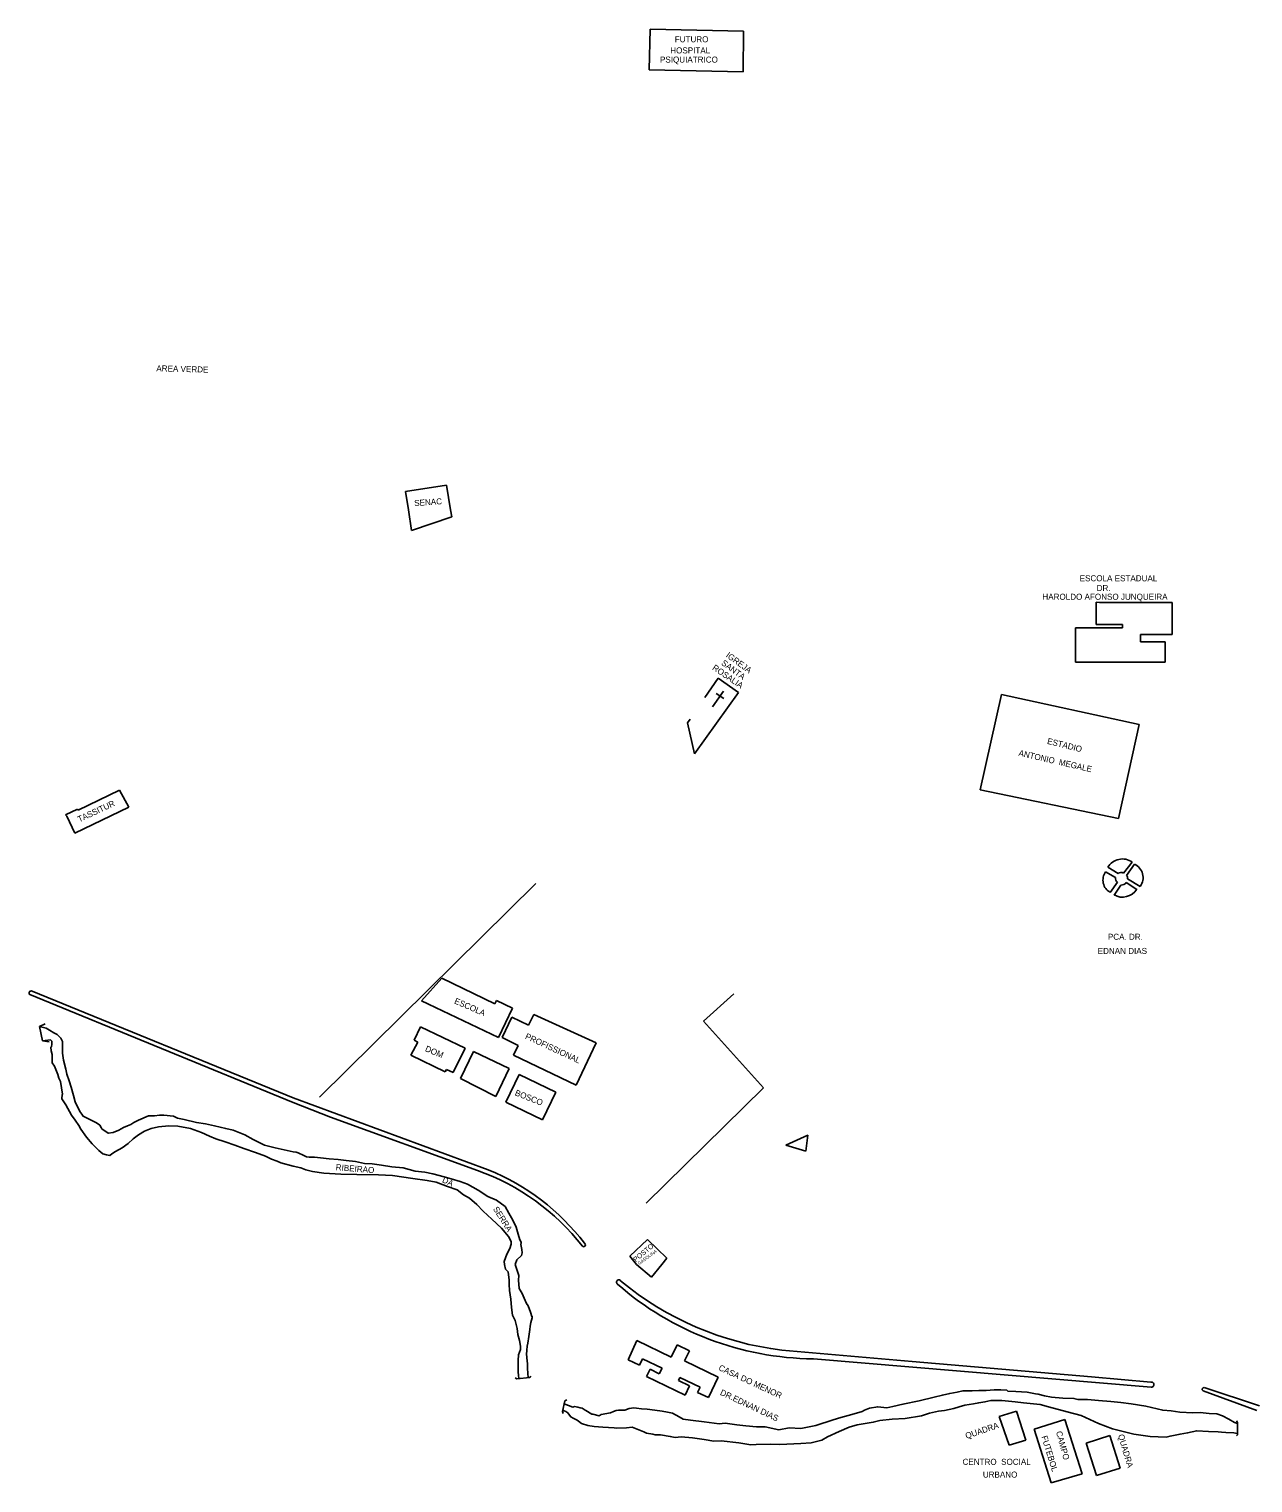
# Model space of a CAD drawing. Extents: x 325899 to 363134, y 7578590 to 7592502.
# Drawn here: x 339906 to 340717, y 7589857 to 7590820 of the extents above; entities that cross this region are included whole.
import ezdxf

# ---------------------------------------------------------------- set-up
doc = ezdxf.new("R2010")
doc.units = 0
for name, color, linetype in [('EDIFEXISTENT', 7, 'Continuous'), ('EDIFIDENTIF', 7, 'Continuous'), ('EDIFOBRAEXIS', 7, 'Continuous')]:
    doc.layers.add(name, color=color, linetype=linetype)

msp = doc.modelspace()

# ---------------------------------------------------------------- linework, layer by layer
at = {"layer": 'EDIFEXISTENT'}
for p, q in [((340317.19, 7590793.38), (340317.81, 7590820.28)), ((340317.81, 7590820.28), (340379.57, 7590818.85)), ((340379.57, 7590818.85), (340379.38, 7590791.94)), ((340379.38, 7590791.94), (340317.19, 7590793.38)), ((340155.84, 7590514.01), (340182.95, 7590518.24)), ((340182.95, 7590518.24), (340185.51, 7590501.91)), ((340157.73, 7590501.91), (340155.84, 7590514.01)), ((340157.73, 7590501.91), (340159.6, 7590488.12)), ((340159.6, 7590488.12), (340186.34, 7590497.29)), ((340186.34, 7590497.29), (340185.51, 7590501.91)), ((340613.33, 7590425.93), (340613.33, 7590440.74)), ((340613.33, 7590440.74), (340615.42, 7590440.43)), ((340615.42, 7590440.43), (340663.68, 7590440.43)), ((340663.68, 7590440.43), (340663.68, 7590419.3)), ((340599.65, 7590400.87), (340599.65, 7590423.61)), ((340599.65, 7590423.61), (340630.66, 7590423.61)), ((340630.66, 7590425.93), (340613.33, 7590425.93)), ((340630.66, 7590423.61), (340630.66, 7590425.93)), ((340663.68, 7590419.3), (340642.69, 7590419.3)), ((340642.69, 7590419.3), (340642.69, 7590414.33)), ((340642.69, 7590414.33), (340658.91, 7590414.33)), ((340658.91, 7590414.33), (340658.91, 7590400.87)), ((340658.91, 7590400.87), (340599.65, 7590400.87)), ((340362.78, 7590390.31), (340354.02, 7590377.55)), ((340376.25, 7590380.89), (340362.78, 7590390.31)), ((340347.07, 7590340.32), (340376.25, 7590380.89)), ((340359.01, 7590371.43), (340366.45, 7590381.73)), ((340361.45, 7590380.18), (340366.65, 7590376.78)), ((340536.46, 7590316.33), (340550.6, 7590379.45)), ((340550.6, 7590379.45), (340641.63, 7590359.66)), ((340344.23, 7590363.29), (340342.44, 7590360.67)), ((340342.44, 7590360.67), (340347.07, 7590340.32)), ((340641.63, 7590359.66), (340628.13, 7590297.31)), ((339938.84, 7590302.94), (339966.38, 7590316.2)), ((339966.38, 7590316.2), (339972.45, 7590304.99)), ((340628.13, 7590297.31), (340536.46, 7590316.33)), ((339930.59, 7590299.91), (339938.36, 7590303.65)), ((339972.45, 7590304.99), (339936.71, 7590287.75)), ((339938.36, 7590303.65), (339938.84, 7590302.94)), ((339931.38, 7590298.87), (339930.59, 7590299.91)), ((339936.71, 7590287.75), (339931.38, 7590298.87)), ((340241.99, 7590254.42), (340098.67, 7590112.92)), ((340166.42, 7590176.72), (340179.82, 7590191.56)), ((340179.82, 7590191.56), (340214.96, 7590174.71)), ((340373.26, 7590181.28), (340353.14, 7590163.2)), ((340217.35, 7590152.31), (340166.42, 7590176.72)), ((340166.42, 7590176.72), (340170.59, 7590174.72)), ((340214.96, 7590174.71), (340215.98, 7590176.84)), ((340215.98, 7590176.84), (340226.65, 7590171.72)), ((340226.65, 7590171.72), (340217.35, 7590152.31)), ((339917.07, 7590161.46), (339913.24, 7590159.66)), ((339913.24, 7590159.66), (339915.35, 7590150.11)), ((340161.37, 7590150.52), (340165.67, 7590159.49)), ((340165.67, 7590159.49), (340195.21, 7590145.33)), ((340226.17, 7590165.75), (340219.69, 7590152.24)), ((340237.21, 7590160.46), (340226.17, 7590165.75)), ((340240.64, 7590167.61), (340237.21, 7590160.46)), ((340282.12, 7590148.81), (340240.64, 7590167.61)), ((340353.14, 7590163.2), (340392.92, 7590118.92)), ((339915.35, 7590150.11), (339919.59, 7590149.57)), ((339919.59, 7590149.57), (339919.59, 7590149.57)), ((340159.26, 7590140.58), (340163.94, 7590149.29)), ((340163.94, 7590149.29), (340161.37, 7590150.52)), ((340219.69, 7590152.24), (340230.34, 7590147.14)), ((340268.69, 7590120.79), (340282.12, 7590148.81)), ((340182.1, 7590129.63), (340159.26, 7590140.58)), ((340195.21, 7590145.33), (340187.41, 7590129.06)), ((340192.1, 7590125.19), (340200.69, 7590143.12)), ((340200.69, 7590143.12), (340224.42, 7590131.74)), ((340230.34, 7590147.14), (340227.23, 7590140.66)), ((340227.23, 7590140.66), (340268.69, 7590120.79)), ((340182.87, 7590131.24), (340182.1, 7590129.63)), ((340187.41, 7590129.06), (340182.87, 7590131.24)), ((340224.42, 7590131.74), (340215.55, 7590113.25)), ((340215.55, 7590113.25), (340192.1, 7590125.19)), ((340222.17, 7590109.57), (340230.93, 7590127.85)), ((340230.93, 7590127.85), (340255.21, 7590116.21)), ((340255.21, 7590116.21), (340246.42, 7590097.88)), ((340392.92, 7590118.92), (340315.23, 7590042.72)), ((340246.42, 7590097.88), (340222.17, 7590109.57)), ((340304.35, 7590007.49), (340316.13, 7590018.45)), ((340316.13, 7590018.45), (340328.92, 7590006.24)), ((340308.82, 7590001.91), (340304.35, 7590007.49)), ((340328.92, 7590006.24), (340325.49, 7590001.91)), ((340308.82, 7590001.91), (340318.68, 7589993.68)), ((340318.68, 7589993.68), (340325.49, 7590001.91)), ((340303.14, 7589938.96), (340308.87, 7589951.76)), ((340308.87, 7589951.76), (340331.72, 7589940.68)), ((340331.72, 7589940.68), (340335.62, 7589948.72)), ((340335.62, 7589948.72), (340343.77, 7589944.77)), ((340310.65, 7589935.32), (340303.14, 7589938.96)), ((340312.73, 7589939.61), (340310.65, 7589935.32)), ((340325.68, 7589933.33), (340312.73, 7589939.61)), ((340343.77, 7589944.77), (340340.56, 7589938.14)), ((340340.56, 7589938.14), (340362.89, 7589927.31)), ((340238.04, 7589927.04), (340238.73, 7589927.96)), ((340315.46, 7589927.89), (340317.73, 7589932.56)), ((340340.96, 7589915.53), (340315.46, 7589927.89)), ((340317.73, 7589932.56), (340323.86, 7589929.59)), ((340323.86, 7589929.59), (340325.68, 7589933.33)), ((340337.51, 7589927.15), (340336.58, 7589925.23)), ((340350.84, 7589920.69), (340337.51, 7589927.15)), ((340362.89, 7589927.31), (340356.34, 7589913.8)), ((340228.37, 7589926.97), (340229.51, 7589926.28)), ((340229.51, 7589926.28), (340238.04, 7589927.04)), ((340336.58, 7589925.23), (340343.93, 7589921.66)), ((340343.93, 7589921.66), (340340.96, 7589915.53)), ((340349.19, 7589917.27), (340350.84, 7589920.69)), ((340261.28, 7589911.6), (340259.69, 7589904.59)), ((340262.53, 7589912.35), (340261.28, 7589911.6)), ((340356.34, 7589913.8), (340349.19, 7589917.27)), ((340259.69, 7589904.59), (340260.28, 7589903.26)), ((340548.99, 7589901.21), (340560.55, 7589904.85)), ((340555.57, 7589882.22), (340548.99, 7589901.21)), ((340560.55, 7589904.85), (340566.58, 7589885.69)), ((340572.25, 7589892.85), (340592.57, 7589899.25)), ((340592.57, 7589899.25), (340603.85, 7589863.42)), ((340706.14, 7589898.42), (340706.94, 7589897.24)), ((340583.43, 7589857.32), (340572.25, 7589892.85)), ((340606.71, 7589883.75), (340622.22, 7589888.63)), ((340622.22, 7589888.63), (340629.03, 7589867.01)), ((340706.84, 7589889.14), (340706.14, 7589888.55)), ((340706.94, 7589897.24), (340706.84, 7589889.14)), ((340566.58, 7589885.69), (340555.57, 7589882.22)), ((340613.52, 7589862.14), (340606.71, 7589883.75)), ((340603.85, 7589863.42), (340583.43, 7589857.32)), ((340629.03, 7589867.01), (340613.52, 7589862.14))]:
    msp.add_line(p, q, dxfattribs=at)
at = {"layer": 'EDIFOBRAEXIS'}
for points in [[(340627.73, 7590260.92), (340620.98, 7590265.11)], [(340637.1, 7590268.53), (340631.26, 7590261.12)], [(340638.54, 7590267.11), (340633.39, 7590259.75)], [(340619.48, 7590262.07), (340626.03, 7590258.28)], [(340627.37, 7590255.16), (340622.6, 7590248.44)], [(340633.18, 7590254.93), (340640.09, 7590250.48)], [(340634, 7590257.36), (340642.4, 7590252.46)], [(340625.14, 7590246.73), (340629.58, 7590253.33)], [(339906.87, 7590180.76), (340081.39, 7590109.4)], [(340081.39, 7590112.47), (339908.38, 7590183.05)], [(339913.24, 7590159.66), (339917.73, 7590158.42), (339919.84, 7590157.29), (339922.87, 7590155.49), (339924.99, 7590154.25), (339927.49, 7590151.85), (339928.49, 7590149.74), (339928.62, 7590147.53), (339928.57, 7590141.94), (339929.17, 7590137.36), (339930.66, 7590131.32), (339931.44, 7590128.01), (339933.03, 7590123.62), (339934.24, 7590119.35), (339935.71, 7590113.84), (339936.87, 7590109.73), (339940.07, 7590103.36), (339941.35, 7590101.66), (339942.17, 7590100.24), (339949.78, 7590096.53), (339950.67, 7590096.1), (339951.62, 7590095.39), (339953.3, 7590094.2), (339954.25, 7590092.78), (339954.55, 7590091.92), (339958.78, 7590088.88), (339962.16, 7590089.48), (339965.77, 7590091.02), (339969.02, 7590092.83), (339971.53, 7590093.78), (339973.81, 7590094.83), (339975.74, 7590096.09), (339978.81, 7590097.52), (339985.52, 7590100.44), (339989.51, 7590100.56), (339992.86, 7590100.83), (339995.58, 7590100.84), (340001.97, 7590100.28), (340004.64, 7590098.94), (340009.19, 7590097.94), (340017.21, 7590096.06), (340023.16, 7590095.11), (340029.22, 7590093.84), (340036.65, 7590092.04), (340041.64, 7590090.86), (340049.3, 7590087.86), (340054.91, 7590084.68), (340062.34, 7590081.02), (340069.37, 7590079.34), (340081.39, 7590076.69)], [(339915.35, 7590150.11), (339920.59, 7590150.76), (339921.42, 7590149.81), (339921.44, 7590148.01), (339921.14, 7590146.25), (339920.73, 7590145.85), (339921.12, 7590143.48), (339921.71, 7590140.99), (339921.65, 7590135.6), (339923.13, 7590133.38), (339925.43, 7590127.84), (339926.14, 7590125.5), (339927.2, 7590123.3), (339928.58, 7590114.75), (339928.32, 7590114.62), (339928.02, 7590111.83), (339930.81, 7590107.79), (339934.42, 7590100.87), (339936.96, 7590097.5), (339939.25, 7590094), (339940.78, 7590091.57), (339944.51, 7590086.38), (339948.11, 7590081.96), (339952.6, 7590077.57), (339955.25, 7590075.37), (339957.69, 7590074.66), (339959.79, 7590074.26), (339961.1, 7590075.19), (339963.55, 7590076.8), (339968.15, 7590079.28), (339971.93, 7590082.15), (339975.23, 7590085.26), (339978.84, 7590087.92), (339982.92, 7590090.26), (339987.31, 7590092.18), (339992.07, 7590093.13), (339998.99, 7590093.77), (340004.87, 7590093.65), (340013.42, 7590092.16), (340020.67, 7590089.46), (340025.84, 7590087.1), (340030.2, 7590085.32), (340036.31, 7590083.16), (340042.6, 7590081.08), (340048.66, 7590078.79), (340056.34, 7590076.24), (340062.91, 7590073.65), (340067.06, 7590071.76), (340070.64, 7590070.39), (340073.25, 7590069.4), (340081.39, 7590067.14)], [(340081.39, 7590112.47), (340210.59, 7590064.71)], [(340203.44, 7590064.3), (340105.98, 7590099.69), (340081.39, 7590109.4)], [(340407.69, 7590081.09), (340422.23, 7590087.65), (340420.81, 7590076.97)], [(340081.39, 7590076.69), (340083.24, 7590076.3), (340084.72, 7590075.9), (340088.33, 7590074.12), (340090.18, 7590073.38), (340091.83, 7590073.18), (340095.41, 7590073.03), (340099.37, 7590072.69), (340105.25, 7590072.03), (340111.04, 7590071.5), (340116.5, 7590070.83), (340122.51, 7590070.32), (340128.63, 7590068.98), (340133.6, 7590068.67), (340139.9, 7590067.88), (340146.59, 7590066.79), (340154.21, 7590065.92), (340162.15, 7590063.76), (340168.44, 7590063.07), (340173.85, 7590062.08), (340181.26, 7590060.15), (340186.06, 7590058.68), (340192.02, 7590057.05), (340196.81, 7590055.12), (340203.97, 7590051.26), (340210.31, 7590046.99), (340216.05, 7590044.53), (340221.71, 7590040.31), (340224.12, 7590035.97), (340226.93, 7590031.28), (340228.98, 7590026.78), (340230.38, 7590021.99), (340231.57, 7590018.38), (340232.41, 7590016.73), (340232.33, 7590016.27), (340232.2, 7590015.34), (340232.73, 7590011.93), (340233.03, 7590009.69), (340232.47, 7590007.96), (340229.57, 7590005.02), (340228.47, 7590001.91)], [(340420.81, 7590076.97), (340407.69, 7590081.09)], [(340221.21, 7590001.91), (340221.07, 7590003.93), (340222.79, 7590008.8), (340224.89, 7590012.67), (340225.63, 7590015.52), (340225.68, 7590017.22), (340223.93, 7590020.47), (340219.42, 7590026.02), (340212.92, 7590032.12), (340207.19, 7590037.3), (340202.88, 7590041.67), (340198.05, 7590045.88), (340194.17, 7590048.22), (340189.89, 7590051.47), (340183.57, 7590053.6), (340176.03, 7590056.62), (340170.17, 7590057.57), (340160.6, 7590058.86), (340147.2, 7590060.9), (340137.76, 7590061.44), (340123.6, 7590061.62), (340112.81, 7590061.9), (340101.72, 7590062.44), (340094.21, 7590063.53), (340089.72, 7590064.75), (340086.32, 7590066.05), (340081.39, 7590067.14)], [(340230.84, 7589926.63), (340230.58, 7589928.58), (340230.38, 7589930.94), (340230.37, 7589934.25), (340230.37, 7589938.38), (340230.67, 7589942.27), (340231.85, 7589945.74), (340231.85, 7589947.94), (340231.34, 7589951.56), (340230.24, 7589955.71), (340229.63, 7589959.71), (340228.44, 7589964.87), (340226.63, 7589968.51), (340226.02, 7589973.49), (340225.43, 7589979.09), (340224.64, 7589984.78), (340224.41, 7589988.8), (340224.4, 7589991.56), (340223.76, 7589997.03), (340222.06, 7589998.85), (340221.21, 7590001.91)], [(340228.47, 7590001.91), (340230.75, 7589994.76), (340230.65, 7589991.69), (340231.09, 7589986.08), (340232.92, 7589982.79), (340234.41, 7589979.68), (340235.78, 7589976.11), (340236.98, 7589974.72), (340238.6, 7589970.4), (340239.46, 7589967.51), (340239.67, 7589967.64), (340239.74, 7589966.6), (340238.76, 7589963.51), (340238.41, 7589961.06), (340238.06, 7589958.88), (340237.68, 7589955.92), (340237.38, 7589954.25), (340236.73, 7589949.92), (340236.43, 7589947.92), (340236.13, 7589945.29), (340236.15, 7589944.68), (340235.98, 7589943.14), (340236.19, 7589940.08), (340236.54, 7589936.11), (340236.45, 7589933.12), (340237.05, 7589926.97)], [(340405.07, 7589945.3), (340491.29, 7589937.78), (340610.17, 7589927.6), (340649.5, 7589924.09)], [(340649.58, 7589920.85), (340425.93, 7589939.51)], [(340260.86, 7589909.77), (340266.59, 7589907.55), (340267.68, 7589907.91), (340269.96, 7589907.53), (340271.33, 7589907.15), (340272.69, 7589906.75), (340274.8, 7589905.49), (340275.1, 7589905.26), (340279.08, 7589902.93), (340279.91, 7589902.86), (340284.04, 7589901.75), (340285.38, 7589902.66), (340291.45, 7589903.71), (340293.57, 7589904.57), (340295.22, 7589905.28), (340296.91, 7589905.56), (340300.91, 7589905.42), (340303.9, 7589906.66), (340306.88, 7589906.97), (340308.68, 7589906.92), (340311.99, 7589906.49), (340315.79, 7589906.2), (340320.93, 7589905.62), (340325.74, 7589904.84), (340329.28, 7589904.26), (340332.52, 7589903.56), (340337, 7589901.14), (340339.66, 7589899.62), (340344.44, 7589898.94), (340353.63, 7589897.74), (340363.4, 7589896.46), (340367.42, 7589897), (340375.22, 7589895.75), (340381.14, 7589895.04), (340388.18, 7589894.57), (340393.97, 7589894.5), (340402.98, 7589892.54), (340409.97, 7589893.77), (340417.59, 7589893.32), (340427.63, 7589895.31), (340438.91, 7589899.17), (340444.02, 7589900.74), (340451.46, 7589902.73), (340458.21, 7589904.61), (340459.73, 7589905.42), (340462.99, 7589906.82), (340468.56, 7589907.81), (340474.48, 7589906.98), (340478.58, 7589907.92), (340485.26, 7589909.38), (340496.01, 7589911.74), (340506.03, 7589914.13), (340511.34, 7589915.48), (340516.27, 7589916.6), (340521.23, 7589917.49), (340524.85, 7589918.26), (340528.69, 7589918.29), (340531.05, 7589918.42), (340535.48, 7589918.63), (340540.39, 7589918.63), (340545.7, 7589918.87), (340550.08, 7589918.97), (340554.05, 7589918.8), (340554.76, 7589918.09), (340559.95, 7589917.8), (340567.49, 7589917.4), (340573.01, 7589916.37), (340574.73, 7589916.12), (340579.11, 7589914.94), (340583.59, 7589914.18), (340591.1, 7589913.41), (340598.44, 7589913.34), (340601.08, 7589912.64), (340607.58, 7589912.47), (340614.67, 7589911.9), (340622.94, 7589911.27), (340629.57, 7589910.65), (340636.31, 7589909.62), (340646.15, 7589908.14), (340657.29, 7589905.42), (340662.98, 7589905.07), (340668.58, 7589904.22), (340677.21, 7589903.68), (340682.19, 7589903.96), (340688.01, 7589903.26), (340693.25, 7589903.01), (340696.87, 7589901.8), (340701.15, 7589899.51), (340704.95, 7589897.41), (340706.94, 7589896.75)], [(340719.64, 7589905.32), (340684.04, 7589918.21)], [(340684.88, 7589920.51), (340721.33, 7589908.41)], [(340260.03, 7589905.43), (340260.88, 7589905.11), (340261.84, 7589904.56), (340263.23, 7589903.67), (340265.01, 7589901.37), (340265.24, 7589901.02), (340266.73, 7589900.19), (340268.2, 7589899.58), (340269.46, 7589898.97), (340270.35, 7589898.29), (340272.38, 7589896.78), (340276.61, 7589895.29), (340280.65, 7589894.69), (340286.37, 7589894.24), (340293.89, 7589893.84), (340295.74, 7589893.64), (340302.12, 7589893.83), (340305.78, 7589894.34), (340313.56, 7589891.16), (340315.41, 7589890.28), (340319.58, 7589889.65), (340321.2, 7589889.1), (340324.74, 7589889.08), (340331.1, 7589888.15), (340334.46, 7589887.42), (340338.23, 7589887.9), (340345.8, 7589887.18), (340353.62, 7589886.1), (340360, 7589885.07), (340364.93, 7589885.21), (340376.58, 7589883.85), (340384.55, 7589882.57), (340387.97, 7589882.88), (340397.43, 7589883.1), (340403.6, 7589882.88), (340417.65, 7589883.45), (340424.35, 7589883.94), (340431.49, 7589885.72), (340435.36, 7589887.95), (340442.89, 7589891.45), (340449.52, 7589894.2), (340454.88, 7589895.82), (340465.53, 7589897.56), (340469.99, 7589898.6), (340478.01, 7589899.62), (340486.76, 7589899.91), (340497.49, 7589901.67), (340502.88, 7589903.43), (340508.85, 7589904.95), (340512.77, 7589905.39), (340518.99, 7589906.58), (340522.41, 7589907.63), (340526.2, 7589908.87), (340531.95, 7589909.69), (340535.41, 7589910.38), (340539.59, 7589910.99), (340543.38, 7589911.88), (340550.8, 7589911.81), (340559.65, 7589911.01), (340565.07, 7589910.29), (340576.05, 7589909.34), (340581.7, 7589907.73), (340593.95, 7589904.4), (340603.29, 7589902.01), (340614.79, 7589896.69), (340624, 7589893.08), (340638.28, 7589889.68), (340648.91, 7589888.18), (340659.64, 7589887.71), (340662.22, 7589888.37), (340668.87, 7589889.65), (340673.76, 7589890.44), (340679.83, 7589891.84), (340687.62, 7589891.42), (340694.15, 7589891.17), (340696.15, 7589891.05), (340699.16, 7589890.62), (340704.48, 7589890.4), (340706.6, 7589890.07), (340706.6, 7589890.07)]]:
    msp.add_lwpolyline(points, dxfattribs=at)
for centre, radius, start, end in [((340630.62, 7590259.36), 11.23, 54.77581, 149.1827), ((340634.7, 7590258.27), 9.64, 322.99558, 66.4748), ((340627.03, 7590256.62), 9.31, 144.20823, 241.54784), ((340628.99, 7590257.7), 3.01, 168.94641, 237.62939), ((340629.62, 7590258.77), 2.86, 55.17613, 131.36573), ((340630.02, 7590257.21), 3.9, 263.54813, 324.25588), ((340631.56, 7590258.01), 2.52, 345.10406, 43.4953), ((340630.63, 7590256.52), 11.22, 240.68884, 327.47486), ((339907.77, 7590181.8), 1.39, 63.9359, 229.0979), ((340152.08, 7589920.17), 153.01, 37.85821, 70.38526), ((340154.43, 7589925.29), 150.3, 37.13368, 68.06104), ((340273.67, 7590014.98), 1.2, 229.02892, 60.84114), ((340297, 7589990.28), 1.54, 36.98265, 239.90914), ((340427.68, 7590139), 199.49, 228.77896, 269.49627), ((340429.42, 7590149.29), 205.44, 230.30968, 263.1928), ((340649.85, 7589922.48), 1.65, 260.40632, 102.42669), ((340684.67, 7589919.29), 1.24, 80.41629, 239.59269)]:
    msp.add_arc(centre, radius, start, end, dxfattribs=at)

# ---------------------------------------------------------------- texts
at = {"layer": 'EDIFIDENTIF'}
for s, p in [('FUTURO', (340334.11, 7590811.55)), ('HOSPITAL', (340331.11, 7590804.15)), ('PSIQUIATRICO', (340324.31, 7590798.07)), ('ESCOLA ESTADUAL', (340602.31, 7590454.52)), ('DR.', (340613.54, 7590448.09)), ('HAROLDO AFONSO JUNQUEIRA', (340577.62, 7590442.27)), ('PCA. DR.', (340621, 7590217.06)), ('EDNAN DIAS', (340614.25, 7590207.69)), ('CENTRO  SOCIAL', (340524.73, 7589869.3)), ('URBANO', (340538.16, 7589860.86))]:
    msp.add_text(s, height=4, dxfattribs=at).set_placement(p)
for s, height, rotation, p in [('AREA VERDE', 4, 358.50669, (339990.66, 7590593.61)), ('SENAC', 4, 3.95193, (340161.65, 7590504.29)), ('ROSALIA', 4, 325.65707, (340358.58, 7590396.36)), ('SANTA', 4, 323.89277, (340364.56, 7590399.58)), ('IGREJA', 4, 323.98289, (340367.57, 7590404.69)), ('ANTONIO  MEGALE', 4, 347.12462, (340561.55, 7590339.05)), ('ESTADIO', 4, 346.0946, (340580.5, 7590346.92)), ('TASSITUR', 4, 25.03632, (339939.7, 7590294.83)), ('ESCOLA', 4, 336.5899, (340187.64, 7590175.07)), ('PROFISSIONAL', 4, 335.00538, (340234.6, 7590151.75)), ('DOM', 4, 336.59253, (340168.35, 7590143.49)), ('BOSCO', 4, 338.41561, (340227.82, 7590114.19)), ('RIBEIRAO', 4, 355.40161, (340109.43, 7590064.52)), ('DA', 4, 335.66619, (340179.66, 7590056.62)), ('SERRA', 4, 302.3699, (340213.49, 7590038.81)), ('POSTO', 3.3, 39.92466, (340308.2, 7590003.42)), ('GASOLINA', 2.067, 35.95764, (340310.64, 7590001.69)), ('CASA DO MENOR', 4, 335.05837, (340362.69, 7589932.22)), ('DR.EDNAN DIAS', 4, 334.75315, (340363.73, 7589915.86)), ('QUADRA', 4, 18.99032, (340527.37, 7589886.4)), ('FUTEBOL', 4, 287.06492, (340576.9, 7589887.98)), ('CAMPO', 4, 285.4918, (340586.56, 7589891.05)), ('QUADRA', 4, 286.41559, (340627.64, 7589888.95))]:
    msp.add_text(s, height=height, rotation=rotation, dxfattribs=at).set_placement(p)

doc.saveas('drawing.dxf')
